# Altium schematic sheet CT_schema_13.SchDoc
size 391 x 385 mm
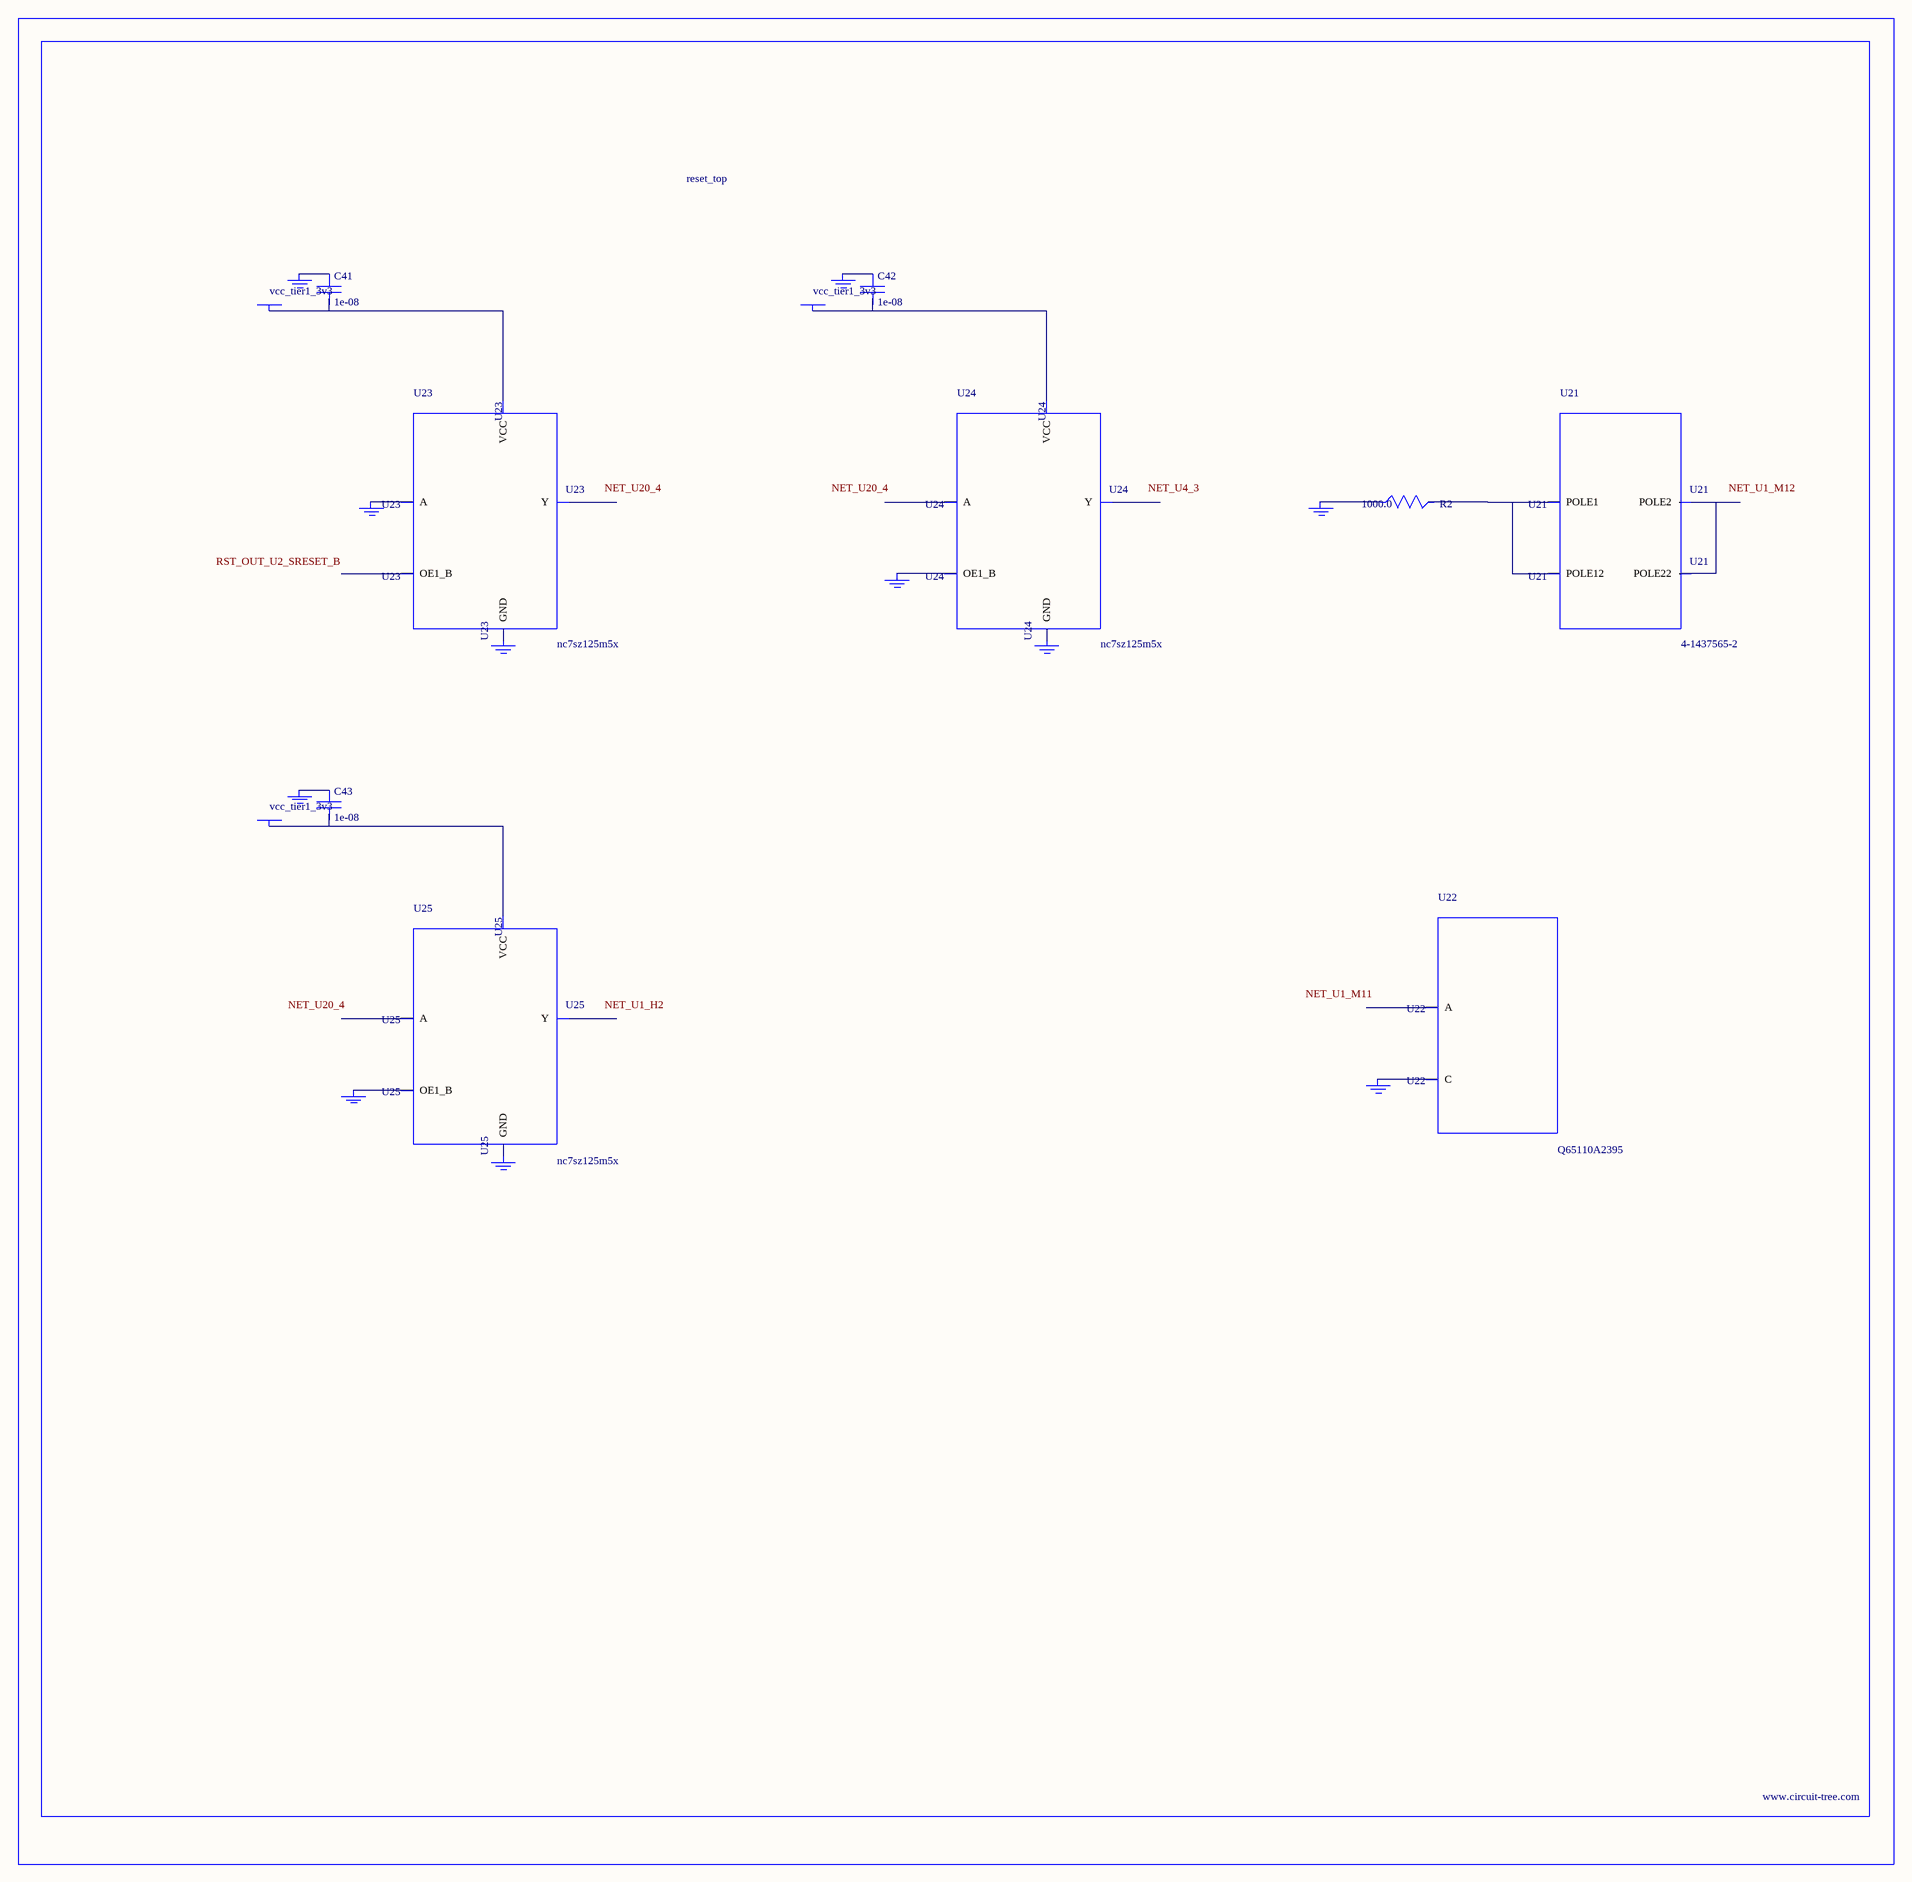
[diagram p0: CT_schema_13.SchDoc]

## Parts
BORDER12  (no value)
C41  1e-08  [C0402]
C42  1e-08  [C0402]
C43  1e-08  [C0402]
GND_INSTANCE_12_0  (no value)
GND_INSTANCE_12_1  (no value)
GND_INSTANCE_12_2  (no value)
GND_INSTANCE_12_3  (no value)
GND_INSTANCE_12_4  (no value)
GND_INSTANCE_12_5  (no value)
GND_INSTANCE_12_6  (no value)
GND_INSTANCE_12_7  (no value)
GND_INSTANCE_12_8  (no value)
GND_INSTANCE_12_9  (no value)
GND_INSTANCE_12_10  (no value)
POWER_INSTANCE_12_0  vcc_tier1_3v3
POWER_INSTANCE_12_1  vcc_tier1_3v3
POWER_INSTANCE_12_2  vcc_tier1_3v3
R2  1000.0  [R0603]
U21  4-1437565-2  [SW_4-1437565-2]
U22  Q65110A2395  [LGM67K-G1J2-24-Z]
U23  nc7sz125m5x  [NC7SZ125M5X]
U24  nc7sz125m5x  [NC7SZ125M5X]
U25  nc7sz125m5x  [NC7SZ125M5X]

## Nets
NetC41_1: C41.1 GND_INSTANCE_12_2.0(GND)
NetC41_2: C41.2 POWER_INSTANCE_12_0.0(PWR) U23.5(VCC)
NetC42_1: C42.1 GND_INSTANCE_12_5.0(GND)
NetC42_2: C42.2 POWER_INSTANCE_12_1.0(PWR) U24.5(VCC)
NetC43_1: C43.1 GND_INSTANCE_12_8.0(GND)
NetC43_2: C43.2 POWER_INSTANCE_12_2.0(PWR) U25.5(VCC)
NetGND_INSTANCE_12_0_0: GND_INSTANCE_12_0.0(GND) R2.1
NetGND_INSTANCE_12_1_0: GND_INSTANCE_12_1.0(GND) U22.C
NetGND_INSTANCE_12_3_0: GND_INSTANCE_12_3.0(GND) U23.2(A)
NetGND_INSTANCE_12_4_0: GND_INSTANCE_12_4.0(GND) U23.3(GND)
NetGND_INSTANCE_12_6_0: GND_INSTANCE_12_6.0(GND) U24.1(OE1_B)
NetGND_INSTANCE_12_7_0: GND_INSTANCE_12_7.0(GND) U24.3(GND)
NetGND_INSTANCE_12_9_0: GND_INSTANCE_12_9.0(GND) U25.1(OE1_B)
NetGND_INSTANCE_12_10_0: GND_INSTANCE_12_10.0(GND) U25.3(GND)
NetR2_2: R2.2 U21.1(POLE1) U21.2(POLE12)
NetU21_3: U21.3(POLE2) U21.4(POLE22)

Not connected (* = marked no-connect by the designer): U22 A; U23 1(OE1_B) 4(Y); U24 2(A) 4(Y); U25 2(A) 4(Y)

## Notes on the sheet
- Labels drawn without touching a wire or pin: NET_U1_H2, NET_U1_M11, NET_U1_M12, NET_U4_3, NET_U20_4, RST_OUT_U2_SRESET_B

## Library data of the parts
BORDER12 = BORDER_PAGE12
C41-C43 = C0402C103K3RAC
GND_INSTANCE_12_0-GND_INSTANCE_12_10 = GND
POWER_INSTANCE_12_0-POWER_INSTANCE_12_2 = PWR
R2 = RC0603JR-071KL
